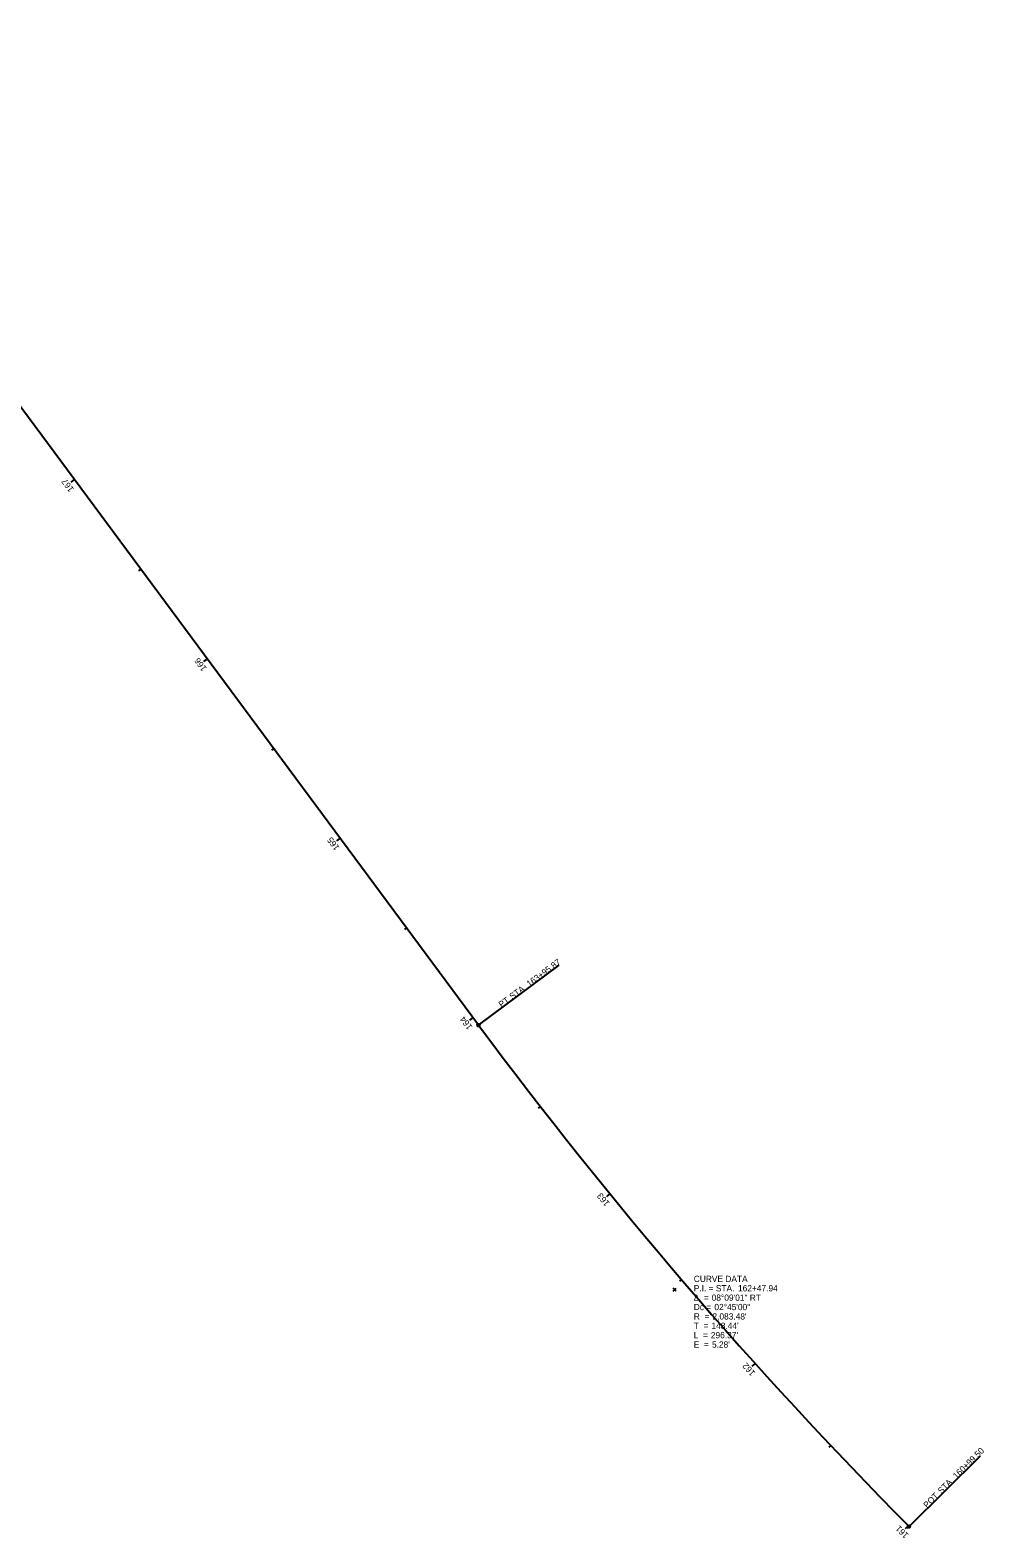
# Model space of a CAD drawing. Extents: x 142407 to 143428, y 484951 to 486303.
# Drawn here: x 143000 to 143428, y 484951 to 485626 of the extents above; entities that cross this region are included whole.
import ezdxf

# ---------------------------------------------------------------- set-up
doc = ezdxf.new("R2010")
doc.units = 0
for name, color, linetype in [('GE_X_Alignment', 7, 'Continuous'), ('GE_X_Alignment_1000_Curve_Data', 7, 'Continuous'), ('GE_X_Alignment_1000_Stations', 7, 'Continuous'), ('GE_X_Alignment_100_Curve_Data', 7, 'Continuous'), ('GE_X_Alignment_100_Stations', 7, 'Continuous'), ('GE_X_Alignment_500_Curve_Data', 7, 'Continuous'), ('GE_X_Alignment_500_Stations', 7, 'Continuous'), ('SV_P_Control_Cells_Set', 7, 'Continuous')]:
    doc.layers.add(name, color=color, linetype=linetype)

msp = doc.modelspace()

# ---------------------------------------------------------------- linework, layer by layer
at = {"layer": 'GE_X_Alignment'}
msp.add_line((143201.27, 485180.76), (142573.01, 486028.27), dxfattribs=at)
msp.add_arc((144874.46, 486422.26), 2083.48, 216.57516, 224.72539, dxfattribs=at)
at = {"layer": 'GE_X_Alignment_1000_Stations'}
for p, q in [((143139.26, 485264.41), (143138.29, 485263.7)), ((143201.27, 485180.76), (143237.42, 485207.56)), ((143394.17, 484956.09), (143426.14, 484987.76))]:
    msp.add_line(p, q, dxfattribs=at)
for centre in [(143201.27, 485180.76), (143394.17, 484956.09)]:
    msp.add_circle(centre, 0.6, dxfattribs=at)
at = {"layer": 'GE_X_Alignment_100_Stations'}
for p, q in [((143020.15, 485425.08), (143018.55, 485423.89)), ((143049.93, 485384.91), (143048.96, 485384.2)), ((143079.7, 485344.75), (143078.1, 485343.56)), ((143109.48, 485304.58), (143108.52, 485303.86)), ((143139.26, 485264.41), (143137.65, 485263.22)), ((143169.03, 485224.25), (143168.07, 485223.53)), ((143201.27, 485180.76), (143237.42, 485207.56)), ((143198.81, 485184.08), (143197.2, 485182.89)), ((143229, 485144.23), (143228.06, 485143.49)), ((143260.14, 485105.11), (143258.59, 485103.85)), ((143292.22, 485066.75), (143291.3, 485065.97)), ((143325.2, 485029.18), (143323.71, 485027.84)), ((143359.07, 484992.4), (143358.2, 484991.58)), ((143394.17, 484956.09), (143426.14, 484987.76)), ((143393.82, 484956.45), (143392.4, 484955.04))]:
    msp.add_line(p, q, dxfattribs=at)
for centre in [(143201.27, 485180.76), (143394.17, 484956.09)]:
    msp.add_circle(centre, 0.6, dxfattribs=at)
at = {"layer": 'GE_X_Alignment_500_Stations'}
for p, q in [((143020.15, 485425.08), (143019.19, 485424.37)), ((143079.7, 485344.75), (143078.74, 485344.03)), ((143139.26, 485264.41), (143137.65, 485263.22)), ((143201.27, 485180.76), (143237.42, 485207.56)), ((143198.81, 485184.08), (143197.84, 485183.36)), ((143260.14, 485105.11), (143259.21, 485104.35)), ((143325.2, 485029.18), (143324.31, 485028.37)), ((143394.17, 484956.09), (143426.14, 484987.76)), ((143393.82, 484956.45), (143392.97, 484955.6))]:
    msp.add_line(p, q, dxfattribs=at)
for centre in [(143201.27, 485180.76), (143394.17, 484956.09)]:
    msp.add_circle(centre, 0.6, dxfattribs=at)
at = {"layer": 'SV_P_Control_Cells_Set'}
for p, q in [((143201.93, 485180.09), (143200.6, 485181.43)), ((143200.6, 485180.09), (143201.93, 485181.43)), ((143289.77, 485061.6), (143288.44, 485062.94)), ((143288.44, 485061.6), (143289.77, 485062.94)), ((143394.84, 484955.43), (143393.5, 484956.76)), ((143393.5, 484955.43), (143394.84, 484956.76))]:
    msp.add_line(p, q, dxfattribs=at)

# ---------------------------------------------------------------- texts
at = {"layer": 'GE_X_Alignment_1000_Curve_Data'}
for s, p in [('CURVE DATA', (143297.72, 485065.63)), ('P.I. = STA. ', (143297.72, 485061.43)), ('162+47.94', (143317.54, 485061.43)), ('Δ  = ', (143297.72, 485057.23)), ('Dc = ', (143297.72, 485053.03)), ('08°09\'01" RT', (143305.74, 485057.23)), ('02°45\'00"', (143306.96, 485053.03)), ('R  = ', (143297.72, 485048.83)), ("2,083.48'", (143306.09, 485048.83)), ('T  = ', (143297.72, 485044.63)), ('L  = ', (143297.72, 485040.43)), ("296.37'", (143305.37, 485040.43)), ("148.44'", (143305.65, 485044.63)), ('E  = ', (143297.72, 485036.23)), ("5.28'", (143305.87, 485036.23))]:
    msp.add_text(s, height=2.8, dxfattribs=at).set_placement(p)
at = {"layer": 'GE_X_Alignment_1000_Stations'}
for s, rotation, p in [('163+95.87', 36.54954, (143224.07, 485197.72)), (' STA. ', 36.54954, (143215.57, 485191.42)), ('PT', 36.54954, (143211.55, 485188.44)), ('160+99.50', 44.72539, (143415.45, 484977.24)), (' STA. ', 44.72539, (143407.93, 484969.79)), ('POT', 44.72539, (143402.22, 484964.13))]:
    msp.add_text(s, height=2.8, rotation=rotation, dxfattribs=at).set_placement(p)
at = {"layer": 'GE_X_Alignment_100_Curve_Data'}
for s, p in [('CURVE DATA', (143297.72, 485065.63)), ('P.I. = STA. ', (143297.72, 485061.43)), ('162+47.94', (143317.54, 485061.43)), ('Δ  = ', (143297.72, 485057.23)), ('Dc = ', (143297.72, 485053.03)), ('08°09\'01" RT', (143305.74, 485057.23)), ('02°45\'00"', (143306.96, 485053.03)), ('R  = ', (143297.72, 485048.83)), ("2,083.48'", (143306.09, 485048.83)), ('T  = ', (143297.72, 485044.63)), ('L  = ', (143297.72, 485040.43)), ("296.37'", (143305.37, 485040.43)), ("148.44'", (143305.65, 485044.63)), ('E  = ', (143297.72, 485036.23)), ("5.28'", (143305.87, 485036.23))]:
    msp.add_text(s, height=2.8, dxfattribs=at).set_placement(p)
at = {"layer": 'GE_X_Alignment_100_Stations'}
for s, rotation, p in [('167', 126.54954, (143020.14, 485420.82)), ('166', 126.54954, (143079.66, 485340.53)), ('165', 126.54954, (143139.18, 485260.24)), ('163+95.87', 36.54954, (143224.07, 485197.72)), (' STA. ', 36.54954, (143215.57, 485191.42)), ('PT', 36.54954, (143211.55, 485188.44)), ('164', 126.54954, (143198.71, 485179.94)), ('163', 129.21163, (143260.24, 485100.97)), ('162', 131.96164, (143325.5, 485025.04)), ('160+99.50', 44.72539, (143415.45, 484977.24)), (' STA. ', 44.72539, (143407.93, 484969.79)), ('POT', 44.72539, (143402.22, 484964.13)), ('161', 134.71164, (143394.23, 484952.42))]:
    msp.add_text(s, height=2.8, rotation=rotation, dxfattribs=at).set_placement(p)
at = {"layer": 'GE_X_Alignment_500_Curve_Data'}
for s, p in [('CURVE DATA', (143297.72, 485065.63)), ('P.I. = STA. ', (143297.72, 485061.43)), ('162+47.94', (143317.54, 485061.43)), ('Δ  = ', (143297.72, 485057.23)), ('Dc = ', (143297.72, 485053.03)), ('08°09\'01" RT', (143305.74, 485057.23)), ('02°45\'00"', (143306.96, 485053.03)), ('R  = ', (143297.72, 485048.83)), ("2,083.48'", (143306.09, 485048.83)), ('T  = ', (143297.72, 485044.63)), ('L  = ', (143297.72, 485040.43)), ("296.37'", (143305.37, 485040.43)), ("148.44'", (143305.65, 485044.63)), ('E  = ', (143297.72, 485036.23)), ("5.28'", (143305.87, 485036.23))]:
    msp.add_text(s, height=2.8, dxfattribs=at).set_placement(p)
at = {"layer": 'GE_X_Alignment_500_Stations'}
for s, rotation, p in [('165', 126.54954, (143139.18, 485260.24)), ('163+95.87', 36.54954, (143224.07, 485197.72)), (' STA. ', 36.54954, (143215.57, 485191.42)), ('PT', 36.54954, (143211.55, 485188.44)), ('160+99.50', 44.72539, (143415.45, 484977.24)), (' STA. ', 44.72539, (143407.93, 484969.79)), ('POT', 44.72539, (143402.22, 484964.13))]:
    msp.add_text(s, height=2.8, rotation=rotation, dxfattribs=at).set_placement(p)

doc.saveas('drawing.dxf')
